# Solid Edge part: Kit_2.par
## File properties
Sűrűség: 0,000 kg/m^3
Pontosság: 0,990
Author: bmolnar
Last saved by: bmolnar
Revision: 77
Username: bmolnar
Dokumentum tartalom típus: 0
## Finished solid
Body 1: solid body, 21 faces, 37 edges, 27 vertices.
  Faces by surface: cylinder 10, plane 9, cone 1, torus 1
  Edges by curve: circle 23, line 14
Bounding box of the edges (mm; curved faces can reach further): 68.000 x 67.800 x 6.000, from (-34, -32.35, 0.65) to (34, 35.45, 6.65).
Cylindrical faces by radius (mm): R1.5 x2, R3 x4, R23.5 x1, R29.65 x1, R32.35 x1, R34 x1
Conical faces (half-angle, radius in mm at the cone's reference point): 45 deg R23 x1
Toroidal faces (ring radius, tube radius in mm): R24.3 r0.8 x1
Planar faces by outward normal: +z 2, -z 5, oblique 2
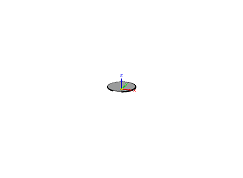
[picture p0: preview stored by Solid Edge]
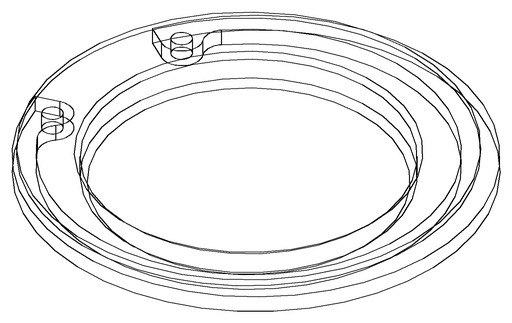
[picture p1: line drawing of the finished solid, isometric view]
